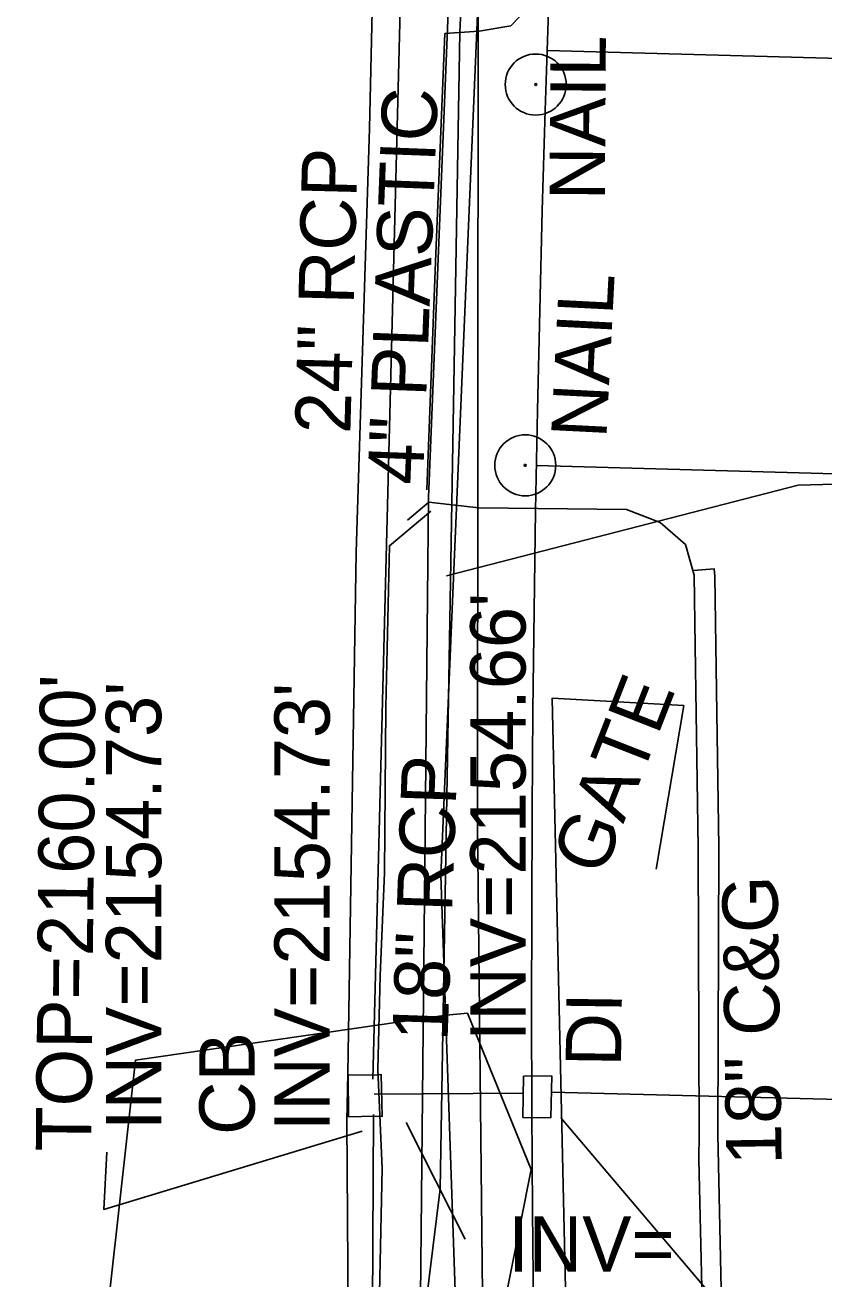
# Model space of a CAD drawing. Extents: x 945964 to 948456, y 631061 to 636061.
# Drawn here: x 946815.5 to 946873.2, y 632869 to 632959.5 of the extents above; entities that cross this region are included whole.
import ezdxf

# ---------------------------------------------------------------- set-up
doc = ezdxf.new("R2010")
doc.units = 0
for name, color, linetype in [('Exist Horizontal Alignment', 7, 'Continuous'), ('Exist Other Culture Fence Line', 7, 'Continuous'), ('Exist Other Culture Gate', 7, 'Continuous'), ('Exist Other Culture Gate Text', 7, 'Continuous'), ('Exist Property Iron Pin CELL', 7, 'Continuous'), ('Exist Property Iron Pin Text', 7, 'Continuous'), ('Exist Right of Way Line', 7, 'Continuous'), ('Exist Roads Change in Surface', 7, 'Continuous'), ('Exist Roads Curbs', 7, 'Continuous'), ('Exist Roads Curbs Text', 7, 'Continuous'), ('Exist Roads EOP', 7, 'Continuous'), ('Exist Roads EOP Other', 7, 'Continuous'), ('Exist Structure Minor Catch Basin', 7, 'Continuous'), ('Exist Structure Minor Catch Basin Text', 7, 'Continuous'), ('Exist Structure Minor Catch Basin Top Elevation', 7, 'Continuous'), ('Exist Structure Minor Drop Inlet', 7, 'Continuous'), ('Exist Structure Minor Drop Inlet Text', 7, 'Continuous'), ('Exist Structure Minor Pipes HDPE 24 Inch', 7, 'Continuous'), ('Exist Structure Minor Pipes RCP 18 Inch', 7, 'Continuous'), ('Exist Structure Minor Pipes RCP 18 Inch Invert', 7, 'Continuous'), ('Exist Structure Minor Pipes RCP 18 Inch Text', 7, 'Continuous'), ('Exist Structure Minor Pipes RCP 24 Inch', 7, 'Continuous'), ('Exist Structure Minor Pipes RCP 24 Inch Invert', 7, 'Continuous'), ('Exist Structure Minor Pipes RCP 24 Inch Text', 7, 'Continuous'), ('Exist Utilities Gas UG Line SUE', 7, 'Continuous'), ('Exist Utilities Gas UG Line SUE Text', 7, 'Continuous'), ('Exist Utilities Telephone UG Cable SUE', 7, 'Continuous'), ('Exist Utilities Telephone UG FO SUE', 7, 'Continuous'), ('Exist Utilities Water UG Line SUE', 7, 'Continuous')]:
    doc.layers.add(name, color=color, linetype=linetype)

# ---------------------------------------------------------------- blocks, each defined once
blk = doc.blocks.new('EXIST PROPERTY IRON PIN')
at = {"layer": 'Exist Property Iron Pin CELL'}
for radius in [0.0441, 0.00141]:
    blk.add_circle((0, 0), radius, dxfattribs=at)

msp = doc.modelspace()

# ---------------------------------------------------------------- linework, layer by layer
at = {"layer": 'Exist Horizontal Alignment'}
msp.add_arc((948718.823, 632879.651), 1909.859, 158.53343, 198.31343, dxfattribs=at)
at = {"layer": 'Exist Other Culture Fence Line'}
msp.add_lwpolyline([(946854.689, 632859.761), (946853.53, 632910.915), (946863.065, 632910.406)], dxfattribs=at)
at = {"layer": 'Exist Other Culture Gate'}
msp.add_lwpolyline([(946863.065, 632910.406), (946861.063, 632898.565)], dxfattribs=at)
at = {"layer": 'Exist Right of Way Line'}
msp.add_line((946853.18, 632957.715), (947115.436, 632950.396), dxfattribs=at)
msp.add_lwpolyline([(946852.399, 632927.725), (947114.599, 632920.408)], dxfattribs=at)
for radius, start in [(2096.278, 158.902582), (1996.278, 171.758283)]:
    msp.add_arc((948848.333, 632890.693), radius, start, 198.31343, dxfattribs=at)
at = {"layer": 'Exist Roads Change in Surface'}
msp.add_lwpolyline([(946845.789, 632958.928), (946845.108, 632942.448), (946844.48, 632925.972)], dxfattribs=at)
at = {"layer": 'Exist Roads Curbs'}
for points in [[(946844.779, 632924.437), (946841.777, 632921.933), (946841.524, 632910.274), (946841.419, 632898.319), (946841.107, 632890.9), (946840.943, 632884.113), (946841.262, 632876.946), (946841.071, 632867.958)], [(946848.24, 632924.668), (946846.092, 632924.924), (946844.62, 632925.089)], [(946848.24, 632924.668), (946858.911, 632924.547), (946861.355, 632923.623), (946863.168, 632922.026), (946863.806, 632919.812), (946863.868, 632914.711), (946864.086, 632900.123), (946864.155, 632879.431)], [(946864.155, 632879.431), (946864.14, 632877.596), (946864.495, 632862.196), (946906.938, 632860.767), (946959.49, 632859.248), (947011.492, 632857.962), (947064.463, 632856.507), (947108.34, 632855.311), (947109.548, 632896.802), (947110.219, 632918.537)]]:
    msp.add_lwpolyline(points, dxfattribs=at)
at = {"layer": 'Exist Roads EOP'}
for points in [[(946858.254, 633144.404), (946855.248, 633126.979), (946854.828, 633123.999), (946852.284, 633103.942), (946849.771, 633081.207), (946849.288, 633078.011), (946848.957, 633074.572), (946846.906, 633052.776), (946844.875, 633032.138), (946843.903, 633021.499), (946843.293, 633011.064), (946842.19, 632997.77), (946841.616, 632984.441), (946841.465, 632979.43), (946840.888, 632976.525), (946840.33, 632952.068), (946839.368, 632921.464), (946838.774, 632883.808), (946838.692, 632880.405), (946838.988, 632838.5)], [(946865.519, 632879.422), (946865.848, 632863.746), (946906.961, 632862.181), (946959.504, 632860.907), (947011.661, 632859.446), (947064.261, 632858.087), (947106.916, 632857.027), (947108.079, 632896.584), (947108.925, 632919.147)]]:
    msp.add_lwpolyline(points, dxfattribs=at)
at = {"layer": 'Exist Roads EOP Other'}
for points in [[(946845.789, 632958.928), (946848.255, 632959.101), (946850.552, 632959.489), (946852.441, 632961.464), (946853.512, 632963.496), (946854.207, 632976.976), (946855.394, 633000.649), (946856.117, 633013.576), (946856.162, 633017.519), (946855.277, 633019.662), (946853.491, 633020.981), (946850.874, 633021.861), (946849.466, 633022.314)], [(946844.62, 632925.089), (946843.082, 632923.782)], [(946865.307, 632919.75), (946865.259, 632920.267), (946863.759, 632920.155)], [(946865.307, 632919.75), (946865.367, 632914.731), (946865.586, 632900.152), (946865.519, 632879.422)]]:
    msp.add_lwpolyline(points, dxfattribs=at)
at = {"layer": 'Exist Structure Minor Catch Basin'}
msp.add_line((946838.825, 632880.681), (946838.788, 632883.71), dxfattribs=at)
msp.add_lwpolyline([(946838.825, 632880.681), (946840.713, 632880.731), (946841.261, 632880.711), (946841.193, 632883.736), (946840.679, 632883.704), (946838.788, 632883.71)], dxfattribs=at)
at = {"layer": 'Exist Structure Minor Drop Inlet'}
msp.add_line((946851.474, 632883.618), (946853.511, 632883.638), dxfattribs=at)
msp.add_lwpolyline([(946853.511, 632883.638), (946853.442, 632880.624), (946851.428, 632880.637), (946851.474, 632883.618)], dxfattribs=at)
at = {"layer": 'Exist Structure Minor Pipes HDPE 24 Inch'}
msp.add_line((947119.025, 632875.576), (946853.505, 632882.472), dxfattribs=at)
at = {"layer": 'Exist Structure Minor Pipes RCP 18 Inch'}
msp.add_line((946851.401, 632882.398), (946840.686, 632882.317), dxfattribs=at)
at = {"layer": 'Exist Structure Minor Pipes RCP 18 Inch Invert'}
msp.add_lwpolyline([(946842.988, 632880.272), (946847.248, 632871.851)], dxfattribs=at)
at = {"layer": 'Exist Structure Minor Pipes RCP 24 Inch'}
for p, q in [((946840.572, 632883.407), (946842.97, 632976.459)), ((946840.268, 632810.062), (946840.632, 632880.854))]:
    msp.add_line(p, q, dxfattribs=at)
at = {"layer": 'Exist Structure Minor Pipes RCP 24 Inch Invert'}
for points in [[(946854.18, 632880.578), (946875.768, 632855.167)], [(946839.8, 632879.641), (946821.141, 632873.991), (946821.349, 632878.131)]]:
    msp.add_lwpolyline(points, dxfattribs=at)
at = {"layer": 'Exist Utilities Gas UG Line SUE'}
for points in [[(946845.505, 632898.106), (946850.735, 633021.39), (946858.894, 633093.639), (946868.461, 633168.181), (946874.183, 633192.213), (946885.657, 633248.38), (946897.008, 633290.102), (946905.354, 633314.297), (946948.475, 633344.781), (946953.347, 633385.574), (946936.814, 633391.163)], [(946845.911, 632919.758), (946871.324, 632926.32), (946916.074, 632927.513), (946954.726, 632926.532), (946990.904, 632925.413), (947031.194, 632924.512), (947071.709, 632923.41), (947120.223, 632919.654), (947102.742, 632971.42), (947090.544, 633013.798), (947082.15, 633043.962)], [(946946.023, 632290.109), (946927.478, 632348.335), (946918.804, 632381.361), (946891.12, 632487.287), (946880.501, 632542.399), (946865.508, 632626.799), (946863.923, 632716.295), (946854.375, 632727.206), (946849.915, 632770.486), (946845.505, 632898.106)]]:
    msp.add_lwpolyline(points, dxfattribs=at)
at = {"layer": 'Exist Utilities Telephone UG Cable SUE'}
for points in [[(946848.573, 632861.076), (946848.152, 632901.787), (946848.195, 632960.212), (946851.511, 633021.852), (946856.12, 633073.431), (946861.866, 633131.993), (946870.69, 633187.612)], [(946641.965, 632809.201), (946660.115, 632804.069), (946680.18, 632808.203), (946774.578, 632828.989), (946817.48, 632831.301), (946823.428, 632884.776), (946845.892, 632888.038), (946847.424, 632888.164), (946852.015, 632876.884), (946848.989, 632861.615)]]:
    msp.add_lwpolyline(points, dxfattribs=at)
at = {"layer": 'Exist Utilities Telephone UG FO SUE'}
msp.add_lwpolyline([(946843.746, 632861.862), (946845.448, 632875.493), (946846.869, 632959.025), (946849.895, 633021.88), (946856.091, 633093.819), (946867.01, 633168.174), (946873.264, 633207.461), (946887.896, 633278.922), (946901.402, 633327.209), (946927.152, 633399.498), (946955.334, 633464.906), (946976.868, 633502.55), (946990.39, 633526.439), (947042.993, 633595.209), (947065.95, 633626.615), (947283.342, 634211.928), (947296.027, 634240.083), (947307.131, 634250.192), (947335.856, 634268.177), (947320.617, 634317.859), (947311.196, 634351.263), (947308.665, 634385.702), (947324.733, 634436.609)], dxfattribs=at)
at = {"layer": 'Exist Utilities Water UG Line SUE'}
msp.add_lwpolyline([(946861.597, 632622.987), (946857.97, 632647.584), (946852.975, 632699.988), (946849.456, 632747.013), (946843.882, 632853.229), (946844.601, 632925.42), (946848.495, 633021.709), (946854.666, 633094.537), (946866.269, 633169.121), (946869.897, 633189.051), (946879.915, 633250.637), (946895.595, 633320.411), (946906.539, 633358.286), (946922.144, 633411.438), (946948.634, 633497.922), (946975.56, 633562.658), (947003.551, 633599.526), (947037.064, 633649.359)], dxfattribs=at)

# ---------------------------------------------------------------- block references
at = {"layer": 'Exist Property Iron Pin CELL', "xscale": 50, "yscale": 50}
for p in [(946852.351, 632955.253), (946851.594, 632927.747)]:
    msp.add_blockref('EXIST PROPERTY IRON PIN', p, dxfattribs=at)

# ---------------------------------------------------------------- texts
at = {"layer": 'Exist Other Culture Gate Text'}
msp.add_text('GATE', height=4, rotation=68.61896, dxfattribs=at).set_placement((946857.161, 632897.935))
at = {"layer": 'Exist Property Iron Pin Text'}
for rotation, p in [(89.63166, (946857.348, 632946.887)), (87.09241, (946857.453, 632929.651))]:
    msp.add_text('NAIL', height=4, rotation=rotation, dxfattribs=at).set_placement(p)
at = {"layer": 'Exist Roads Curbs Text'}
msp.add_text('18" C&G', height=4, rotation=90.85743, dxfattribs=at).set_placement((946870.127, 632877.225))
at = {"layer": 'Exist Structure Minor Catch Basin Text'}
msp.add_text('CB', height=4, rotation=90.00002, dxfattribs=at).set_placement((946832.044, 632879.375))
at = {"layer": 'Exist Structure Minor Catch Basin Top Elevation'}
msp.add_text("TOP=2160.00'", height=4, rotation=89.48678, dxfattribs=at).set_placement((946820.225, 632878.153))
at = {"layer": 'Exist Structure Minor Drop Inlet Text'}
msp.add_text('DI', height=4, rotation=89.21444, dxfattribs=at).set_placement((946858.51, 632884.296))
at = {"layer": 'Exist Structure Minor Pipes RCP 18 Inch Invert'}
for s, rotation, p in [("INV=2154.66'", 90.00002, (946851.62, 632886.145)), ('INV=', 0.00002, (946850.36, 632869.507))]:
    msp.add_text(s, height=4, rotation=rotation, dxfattribs=at).set_placement(p)
at = {"layer": 'Exist Structure Minor Pipes RCP 18 Inch Text'}
msp.add_text('18" RCP', height=4, rotation=87.98926, dxfattribs=at).set_placement((946845.978, 632886.11))
at = {"layer": 'Exist Structure Minor Pipes RCP 24 Inch Invert'}
for p in [(946825.288, 632879.725), (946837.466, 632879.643)]:
    msp.add_text("INV=2154.73'", height=4, rotation=90.00002, dxfattribs=at).set_placement(p)
at = {"layer": 'Exist Structure Minor Pipes RCP 24 Inch Text'}
msp.add_text('24" RCP', height=4, rotation=88.52389, dxfattribs=at).set_placement((946838.955, 632929.998))
at = {"layer": 'Exist Utilities Gas UG Line SUE Text'}
msp.add_text('4" PLASTIC ', height=4, rotation=87.81487, dxfattribs=at).set_placement((946844.193, 632926.303))

doc.saveas('drawing.dxf')
